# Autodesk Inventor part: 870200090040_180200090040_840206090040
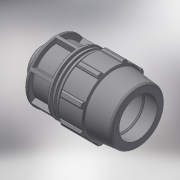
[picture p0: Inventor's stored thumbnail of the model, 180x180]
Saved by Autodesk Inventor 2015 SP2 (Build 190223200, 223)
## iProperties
Created: 2017-02
Part Number: 870200090040_180200090040_840206090040
Material: Generic
Description: PLASSON MALE ADAPTOR 90-4"
Document SubType Name: Modeling
Designer: KIM
Mass: 964.158 g
Surface Area: 1468.9 cm^2
Volume: 964.158 cm^3
Density: 1 g/cm^3
Appearance: Default
Author: KIM
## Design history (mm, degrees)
derived "87020.ipt"
feature "Solid1::87020.ipt"
tag "TaggingFeature1"
body "Solid1"
other parameters: "d4" = 34, "d5" = 59.5, "d7" = 152, "d8" = 114, "d9" = 34, "d11" = 6.8, "d12" = 121.6, "d13" = 120 deg, "d14" = 117, "d15" = 6 deg, "d16" = 136.8, "d18" = 4.5, "d19" = 35 deg, "d20" = 17.5 deg, "d21" = 141.36, "d23" = 0, "d25" = 360 deg, "d27" = 3.04, "d34" = 7.6, "d36" = 0, "d42" = 59.5, "d43" = 4.56, "d46" = 2.7, "d49" = 169, "d51" = 238, "d52" = 38, "d53" = 1.8, "d55" = 360 deg, "d57" = 113.03, "d58" = 79.121, "d59" = 47.6, "d61" = 134.064, "d62" = 3.96, "d63" = 3.96, "d66" = 7.92, "E_" = 152, "H_" = 238, "l_" = 169, "l_2" = 38, "R_" = 113.03, "d60" = 19.8
